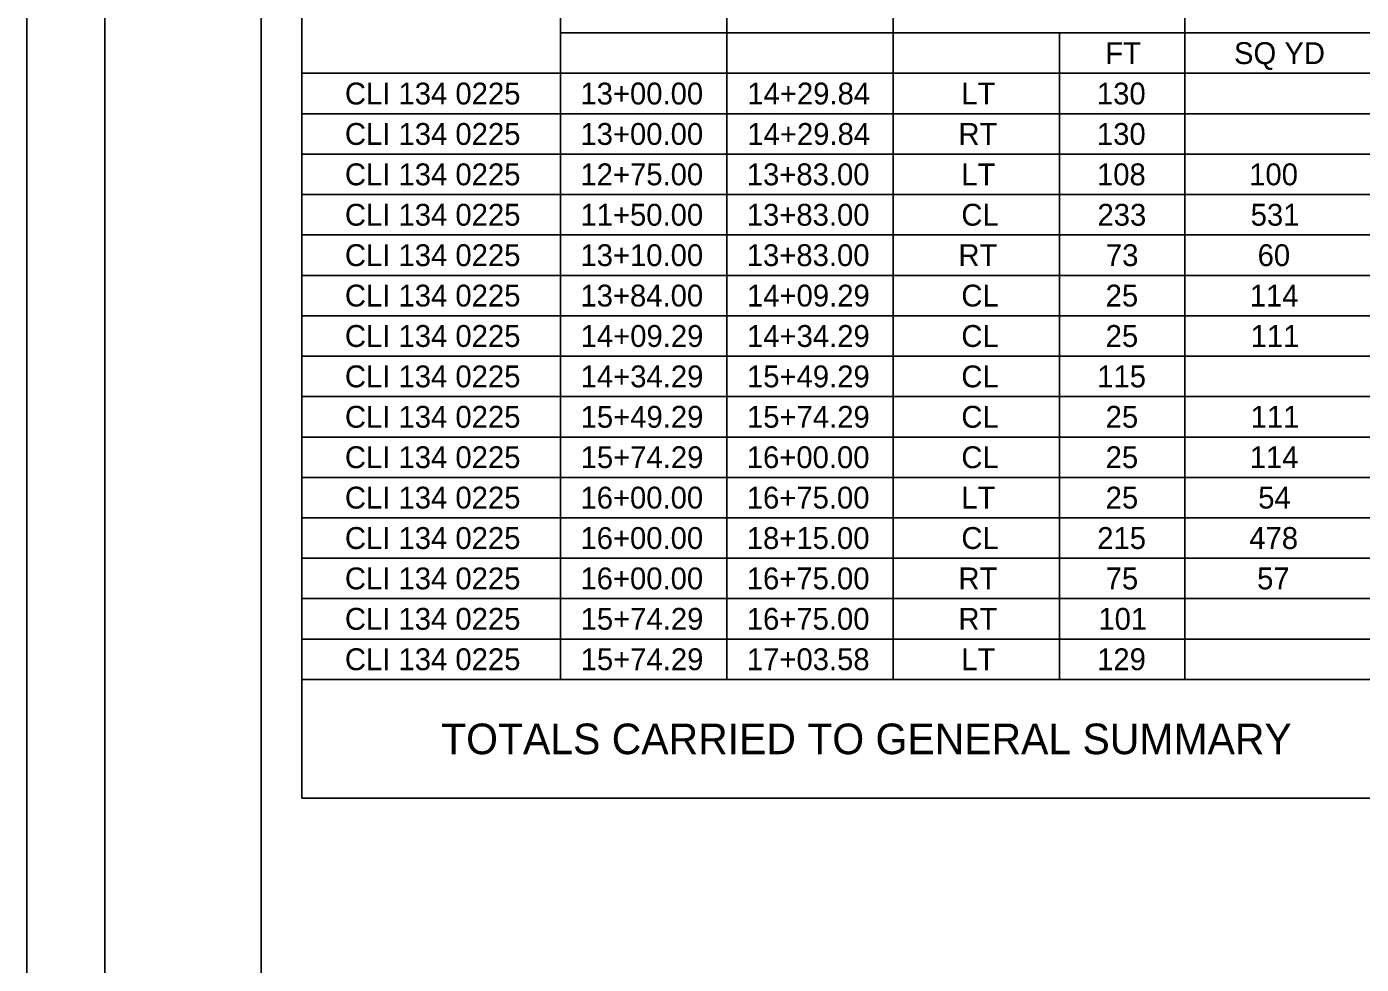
# Model space of a CAD drawing. Extents: x -27.3 to 69.3, y 0 to 30.
# Drawn here: x 0 to 8.54, y 12.94 to 18.94 of the extents above; entities that cross this region are included whole.
import ezdxf

# ---------------------------------------------------------------- set-up
doc = ezdxf.new("R2010")
doc.units = 0
for name, color, linetype in [('Default', 7, 'Continuous'), ('SH_Border', 7, 'Continuous'), ('SH_Cut_Line', 7, 'Continuous')]:
    doc.layers.add(name, color=color, linetype=linetype)

msp = doc.modelspace()

# ---------------------------------------------------------------- linework, layer by layer
at = {"layer": 'Default'}
for p, q in [((1.762, 21.2276), (1.762, 14.0028)), ((3.4163, 20.969), (3.4163, 14.7633)), ((5.5457, 20.969), (5.5457, 14.7633)), ((7.4129, 20.969), (7.4129, 14.7633)), ((4.481, 19.6761), (4.481, 14.7633)), ((3.4163, 18.9004), (26.6918, 18.9004)), ((6.6103, 18.9004), (6.6103, 14.7633)), ((1.762, 18.6419), (29.8694, 18.6419)), ((1.762, 18.3833), (26.6918, 18.3833)), ((1.762, 18.1247), (29.8694, 18.1247)), ((1.762, 17.8661), (29.8694, 17.8661)), ((1.762, 17.6076), (29.8694, 17.6076)), ((1.762, 17.349), (29.8694, 17.349)), ((1.762, 17.0904), (29.8694, 17.0904)), ((1.762, 16.8319), (29.8694, 16.8319)), ((1.762, 16.5733), (29.8694, 16.5733)), ((1.762, 16.3147), (29.8694, 16.3147)), ((1.762, 16.0562), (29.8694, 16.0562)), ((1.762, 15.7976), (29.8694, 15.7976)), ((1.762, 15.539), (29.8694, 15.539)), ((1.762, 15.2804), (29.8694, 15.2804)), ((1.762, 15.0219), (26.6918, 15.0219)), ((1.762, 14.7633), (26.6918, 14.7633)), ((1.762, 14.0028), (29.8694, 14.0028))]:
    msp.add_line(p, q, dxfattribs=at)
at = {"layer": 'SH_Border'}
for points in [[(0.5, 21.5), (1.5, 21.5), (1.5, 0.5), (0.5, 0.5)], [(1.5, 21.5), (33.5, 21.5), (33.5, 0.5), (1.5, 0.5)]]:
    msp.add_lwpolyline(points, close=True, dxfattribs=at)
at = {"layer": 'SH_Cut_Line'}
msp.add_lwpolyline([(0, 0), (34, 0), (34, 22), (0, 22)], close=True, dxfattribs=at)

# ---------------------------------------------------------------- texts
at = {"layer": 'Default'}
for s, height, p in [('FT', 0.13993, (6.9031, 18.7012)), ('SQ YD', 0.13993, (7.7271, 18.7012)), ('CLI 134 0225', 0.139932, (2.0366, 18.4426)), ('13+00.00', 0.13993, (3.5439, 18.4426)), ('14+29.84', 0.13993, (4.6122, 18.4426)), ('LT', 0.13993, (5.9819, 18.4426)), ('130', 0.13993, (6.8495, 18.4426)), ('CLI 134 0225', 0.139932, (2.0366, 18.184)), ('13+00.00', 0.13993, (3.5439, 18.184)), ('14+29.84', 0.13993, (4.6122, 18.184)), ('RT', 0.13993, (5.9631, 18.184)), ('130', 0.13993, (6.8495, 18.184)), ('CLI 134 0225', 0.139932, (2.0366, 17.9255)), ('12+75.00', 0.13993, (3.5439, 17.9255)), ('13+83.00', 0.13993, (4.6086, 17.9255)), ('LT', 0.13993, (5.9819, 17.9255)), ('108', 0.13993, (6.8501, 17.9255)), ('100', 0.13993, (7.8241, 17.9255)), ('CLI 134 0225', 0.139932, (2.0366, 17.6669)), ('11+50.00', 0.13993, (3.5439, 17.6669)), ('13+83.00', 0.13993, (4.6086, 17.6669)), ('CL', 0.13993, (5.982, 17.6669)), ('233', 0.13993, (6.8532, 17.6669)), ('531', 0.13993, (7.8336, 17.6669)), ('CLI 134 0225', 0.139932, (2.0366, 17.4083)), ('13+10.00', 0.13993, (3.5439, 17.4083)), ('13+83.00', 0.13993, (4.6086, 17.4083)), ('RT', 0.13993, (5.9631, 17.4083)), ('73', 0.13993, (6.9073, 17.4083)), ('60', 0.13993, (7.8782, 17.4083)), ('CLI 134 0225', 0.139932, (2.0366, 17.1497)), ('13+84.00', 0.13993, (3.5439, 17.1497)), ('14+09.29', 0.13993, (4.61, 17.1497)), ('CL', 0.13993, (5.982, 17.1497)), ('25', 0.13993, (6.9057, 17.1497)), ('114', 0.13993, (7.8277, 17.1497)), ('CLI 134 0225', 0.139932, (2.0366, 16.8912)), ('14+09.29', 0.13993, (3.5453, 16.8912)), ('14+34.29', 0.13993, (4.61, 16.8912)), ('CL', 0.13993, (5.982, 16.8912)), ('25', 0.13993, (6.9057, 16.8912)), ('111', 0.13993, (7.8336, 16.8912)), ('CLI 134 0225', 0.139932, (2.0366, 16.6326)), ('14+34.29', 0.13993, (3.5453, 16.6326)), ('15+49.29', 0.13993, (4.61, 16.6326)), ('CL', 0.13993, (5.982, 16.6326)), ('115', 0.13993, (6.8516, 16.6326)), ('CLI 134 0225', 0.139932, (2.0366, 16.374)), ('15+49.29', 0.13993, (3.5453, 16.374)), ('15+74.29', 0.13993, (4.61, 16.374)), ('CL', 0.13993, (5.982, 16.374)), ('25', 0.13993, (6.9057, 16.374)), ('111', 0.13993, (7.8336, 16.374)), ('CLI 134 0225', 0.139932, (2.0366, 16.1155)), ('15+74.29', 0.13993, (3.5453, 16.1155)), ('16+00.00', 0.13993, (4.6086, 16.1155)), ('CL', 0.13993, (5.982, 16.1155)), ('25', 0.13993, (6.9057, 16.1155)), ('114', 0.13993, (7.8277, 16.1155)), ('CLI 134 0225', 0.139932, (2.0366, 15.8569)), ('16+00.00', 0.13993, (3.5439, 15.8569)), ('16+75.00', 0.13993, (4.6086, 15.8569)), ('LT', 0.13993, (5.9819, 15.8569)), ('25', 0.13993, (6.9057, 15.8569)), ('54', 0.13993, (7.8819, 15.8569)), ('CLI 134 0225', 0.139932, (2.0366, 15.5983)), ('16+00.00', 0.13993, (3.5439, 15.5983)), ('18+15.00', 0.13993, (4.6086, 15.5983)), ('CL', 0.13993, (5.982, 15.5983)), ('215', 0.13993, (6.8516, 15.5983)), ('478', 0.13993, (7.8247, 15.5983)), ('CLI 134 0225', 0.139932, (2.0366, 15.3398)), ('16+00.00', 0.13993, (3.5439, 15.3398)), ('16+75.00', 0.13993, (4.6086, 15.3398)), ('RT', 0.13993, (5.9631, 15.3398)), ('75', 0.13993, (6.9057, 15.3398)), ('57', 0.13993, (7.8749, 15.3398)), ('CLI 134 0225', 0.139932, (2.0366, 15.0812)), ('15+74.29', 0.13993, (3.5453, 15.0812)), ('16+75.00', 0.13993, (4.6086, 15.0812)), ('RT', 0.13993, (5.9631, 15.0812)), ('101', 0.13993, (6.859, 15.0812)), ('CLI 134 0225', 0.139932, (2.0366, 14.8226)), ('15+74.29', 0.13993, (3.5453, 14.8226)), ('17+03.58', 0.13993, (4.6092, 14.8226)), ('LT', 0.13993, (5.9819, 14.8226)), ('129', 0.13993, (6.8509, 14.8226)), ('TOTALS CARRIED TO GENERAL SUMMARY', 0.195905, (2.6526, 14.2851))]:
    msp.add_text(s, height=height, dxfattribs=at).set_placement(p)

doc.saveas('drawing.dxf')
